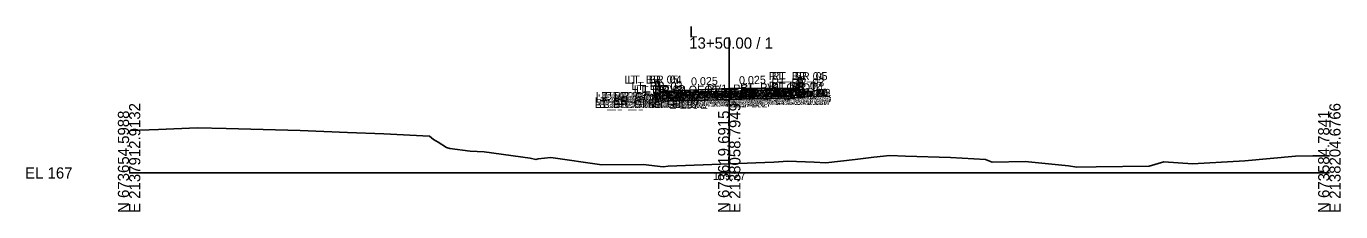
# Model space of a CAD drawing. Extents: x -26 to 5503, y -10 to 7033.
# Drawn here: x -25.7 to 302.8, y 4490.3 to 4536.7 of the extents above; entities that cross this region are included whole.
import ezdxf

# ---------------------------------------------------------------- set-up
doc = ezdxf.new("R2010")
doc.units = 0
for name, color, linetype in [('Default', 7, 'Continuous'), ('Exist Cross Section Cell', 7, 'Continuous'), ('Exist XS Center Line Elevation Label', 7, 'Continuous'), ('Exist XS Ground Line', 7, 'Continuous'), ('Prop CMT Concrete Structures', 7, 'Continuous'), ('Prop XS SE Text', 7, 'Continuous')]:
    doc.layers.add(name, color=color, linetype=linetype)

msp = doc.modelspace()

# ---------------------------------------------------------------- linework, layer by layer
at = {"layer": 'Exist Cross Section Cell'}
for p, q in [((150, 4500), (150, 4533.88)), ((0, 4500), (150, 4500)), ((150, 4500), (300, 4500))]:
    msp.add_line(p, q, dxfattribs=at)
at = {"layer": 'Exist XS Ground Line'}
for p, q in [((0.3, 4510.66), (7.34, 4510.87)), ((7.34, 4510.87), (17.04, 4511.29)), ((17.04, 4511.29), (24.28, 4511.09)), ((24.28, 4511.09), (42.73, 4510.6)), ((42.73, 4510.6), (54.62, 4510.13)), ((54.62, 4510.13), (63.65, 4509.75)), ((63.65, 4509.75), (75.1, 4509.21)), ((75.1, 4509.21), (76.09, 4508.33)), ((76.09, 4508.33), (77.25, 4507.69)), ((77.25, 4507.69), (79.37, 4506.33)), ((79.37, 4506.33), (80.21, 4506.12)), ((80.21, 4506.12), (85.28, 4505.47)), ((85.28, 4505.47), (88.71, 4505.31)), ((88.71, 4505.31), (100.28, 4503.68)), ((186.17, 4503.99), (190.12, 4504.34)), ((190.12, 4504.34), (194.06, 4504.2)), ((194.06, 4504.2), (205.31, 4503.89)), ((278.91, 4503.01), (291.58, 4504.19)), ((291.58, 4504.19), (295.84, 4504.31)), ((295.84, 4504.31), (300, 4504.25)), ((100.28, 4503.68), (101.68, 4503.38)), ((101.68, 4503.38), (102.21, 4503.51)), ((102.21, 4503.51), (105.38, 4503.9)), ((105.38, 4503.9), (118.12, 4502)), ((118.12, 4502), (128.48, 4502.12)), ((128.48, 4502.12), (133.53, 4501.5)), ((133.53, 4501.5), (134.78, 4501.66)), ((134.78, 4501.66), (150, 4502.27)), ((150, 4502.27), (161.13, 4502.71)), ((161.13, 4502.71), (164.63, 4502.91)), ((164.63, 4502.91), (171.23, 4502.74)), ((171.23, 4502.74), (174.12, 4502.5)), ((174.12, 4502.5), (181.48, 4503.34)), ((181.48, 4503.34), (186.17, 4503.99)), ((205.31, 4503.89), (214.07, 4503.38)), ((214.07, 4503.38), (215.76, 4502.68)), ((215.76, 4502.68), (224, 4502.84)), ((224, 4502.84), (234.82, 4501.75)), ((234.82, 4501.75), (236.88, 4501.48)), ((236.88, 4501.48), (241.75, 4501.55)), ((241.75, 4501.55), (254.97, 4501.69)), ((254.97, 4501.69), (258.63, 4502.77)), ((258.63, 4502.77), (265.78, 4502.28)), ((265.78, 4502.28), (278.91, 4503.01))]:
    msp.add_line(p, q, dxfattribs=at)
at = {"layer": 'Prop CMT Concrete Structures'}
for p, q in [((131.67, 4520.32), (131.69, 4522.88)), ((132.54, 4522.9), (131.69, 4522.88)), ((132.54, 4522.9), (132.69, 4520.34)), ((159.19, 4520.66), (156.18, 4520.59)), ((159.19, 4520.41), (159.19, 4520.66)), ((159.22, 4520.67), (159.22, 4520.67)), ((162.26, 4520.74), (159.25, 4520.67)), ((159.25, 4520.67), (159.26, 4520.41)), ((162.26, 4520.48), (162.26, 4520.74)), ((162.29, 4520.74), (162.29, 4520.74)), ((165.33, 4520.82), (162.32, 4520.74)), ((162.32, 4520.74), (162.33, 4520.49)), ((165.34, 4520.56), (165.33, 4520.82)), ((168.37, 4520.89), (165.36, 4520.82)), ((165.39, 4520.82), (165.4, 4520.56)), ((167.31, 4521.21), (167.33, 4523.77)), ((167.32, 4520.87), (167.31, 4521.21)), ((168.19, 4523.79), (167.33, 4523.77)), ((168.19, 4523.79), (168.34, 4521.23)), ((168.35, 4520.89), (168.34, 4521.06)), ((168.37, 4520.89), (168.43, 4520.83)), ((168.48, 4518.91), (168.43, 4520.83)), ((131.66, 4519.98), (131.59, 4519.91)), ((131.64, 4517.99), (131.59, 4519.91)), ((131.64, 4517.99), (131.71, 4517.93)), ((134.63, 4520.05), (131.66, 4519.98)), ((131.68, 4519.98), (131.67, 4520.32)), ((131.71, 4517.93), (134.65, 4518)), ((132.7, 4520), (132.69, 4520.34)), ((134.64, 4519.79), (134.61, 4519.76)), ((134.61, 4519.76), (134.61, 4519.52)), ((134.68, 4519.45), (134.61, 4519.52)), ((134.64, 4519.79), (134.63, 4520.05)), ((134.65, 4518), (134.71, 4518.07)), ((134.66, 4520.05), (134.66, 4520.05)), ((134.68, 4519.45), (134.74, 4519.52)), ((134.71, 4518.07), (134.68, 4519.45)), ((134.71, 4518.07), (134.68, 4519.45)), ((137.7, 4520.13), (134.7, 4520.05)), ((134.7, 4520.05), (134.7, 4519.8)), ((134.7, 4519.8), (134.74, 4519.76)), ((134.71, 4518.07), (134.78, 4518.01)), ((134.74, 4519.52), (134.74, 4519.76)), ((134.78, 4518.01), (137.72, 4518.08)), ((137.71, 4519.87), (137.68, 4519.84)), ((137.68, 4519.84), (137.68, 4519.59)), ((137.75, 4519.53), (137.68, 4519.59)), ((137.71, 4519.87), (137.7, 4520.13)), ((137.72, 4518.08), (137.78, 4518.14)), ((137.73, 4520.13), (137.73, 4520.13)), ((137.73, 4520.13), (137.73, 4520.13)), ((137.75, 4519.53), (137.81, 4519.6)), ((137.78, 4518.14), (137.75, 4519.53)), ((137.78, 4518.14), (137.75, 4519.53)), ((140.77, 4520.2), (137.77, 4520.13)), ((137.77, 4520.13), (137.77, 4519.87)), ((137.77, 4519.87), (137.81, 4519.84)), ((137.78, 4518.14), (137.85, 4518.08)), ((137.81, 4519.6), (137.81, 4519.84)), ((137.85, 4518.08), (140.79, 4518.16)), ((140.78, 4519.95), (140.75, 4519.92)), ((140.75, 4519.92), (140.75, 4519.67)), ((140.82, 4519.61), (140.75, 4519.67)), ((140.78, 4519.95), (140.77, 4520.2)), ((140.79, 4518.16), (140.86, 4518.22)), ((140.8, 4520.2), (140.8, 4520.2)), ((140.8, 4520.2), (140.8, 4520.2)), ((140.82, 4519.61), (140.88, 4519.67)), ((140.85, 4518.22), (140.82, 4519.61)), ((140.85, 4518.22), (140.82, 4519.61)), ((143.84, 4520.28), (140.84, 4520.21)), ((140.84, 4520.21), (140.84, 4519.95)), ((140.84, 4519.95), (140.88, 4519.92)), ((140.85, 4518.22), (140.92, 4518.16)), ((140.88, 4519.67), (140.88, 4519.92)), ((140.92, 4518.16), (143.86, 4518.23)), ((143.85, 4520.02), (143.82, 4519.99)), ((143.82, 4519.99), (143.82, 4519.75)), ((143.89, 4519.68), (143.82, 4519.75)), ((143.85, 4520.02), (143.84, 4520.28)), ((143.86, 4518.23), (143.93, 4518.3)), ((143.87, 4520.28), (143.87, 4520.28)), ((143.88, 4520.28), (143.88, 4520.28)), ((143.89, 4519.68), (143.95, 4519.75)), ((143.92, 4518.3), (143.89, 4519.68)), ((143.93, 4518.3), (143.89, 4519.68)), ((146.91, 4520.36), (143.91, 4520.28)), ((143.91, 4520.28), (143.91, 4520.03)), ((143.91, 4520.03), (143.95, 4520)), ((143.93, 4518.3), (143.99, 4518.24)), ((143.95, 4519.75), (143.95, 4520)), ((143.99, 4518.24), (146.93, 4518.31)), ((146.92, 4520.1), (146.89, 4520.07)), ((146.89, 4520.07), (146.9, 4519.82)), ((146.96, 4519.76), (146.9, 4519.82)), ((146.92, 4520.1), (146.91, 4520.36)), ((146.93, 4518.31), (147, 4518.37)), ((146.95, 4520.36), (146.95, 4520.36)), ((146.95, 4520.36), (146.95, 4520.36)), ((146.96, 4519.76), (147.02, 4519.83)), ((147, 4518.37), (146.96, 4519.76)), ((147, 4518.37), (146.96, 4519.76)), ((149.99, 4520.43), (146.98, 4520.36)), ((146.98, 4520.36), (146.99, 4520.1)), ((146.99, 4520.1), (147.02, 4520.07)), ((147, 4518.37), (147.06, 4518.31)), ((147.02, 4519.83), (147.02, 4520.07)), ((147.06, 4518.31), (150.01, 4518.39)), ((149.99, 4520.18), (149.96, 4520.15)), ((149.96, 4520.15), (149.97, 4519.9)), ((150.03, 4519.84), (149.97, 4519.9)), ((149.99, 4520.18), (149.99, 4520.43)), ((150.01, 4518.39), (150.07, 4518.45)), ((150.02, 4520.44), (150.02, 4520.44)), ((150.02, 4520.44), (150.02, 4520.44)), ((150.03, 4519.84), (150.1, 4519.9)), ((150.07, 4518.45), (150.03, 4519.84)), ((150.07, 4518.45), (150.03, 4519.84)), ((151.55, 4520.47), (150.05, 4520.44)), ((150.05, 4520.44), (150.06, 4520.18)), ((150.06, 4520.18), (150.09, 4520.15)), ((150.07, 4518.45), (150.13, 4518.39)), ((150.1, 4519.9), (150.09, 4520.15)), ((150.13, 4518.39), (151.6, 4518.43)), ((153.05, 4520.51), (151.55, 4520.47)), ((151.6, 4518.43), (153.07, 4518.46)), ((153.05, 4520.25), (153.02, 4520.22)), ((153.02, 4520.22), (153.03, 4519.98)), ((153.1, 4519.91), (153.03, 4519.98)), ((153.05, 4520.25), (153.05, 4520.51)), ((153.07, 4518.46), (153.13, 4518.53)), ((153.08, 4520.51), (153.08, 4520.51)), ((153.09, 4519.91), (153.16, 4519.98)), ((153.13, 4518.53), (153.09, 4519.91)), ((153.13, 4518.53), (153.1, 4519.91)), ((156.12, 4520.59), (153.11, 4520.51)), ((153.11, 4520.51), (153.12, 4520.26)), ((153.12, 4520.26), (153.15, 4520.23)), ((153.13, 4518.53), (153.19, 4518.47)), ((153.16, 4519.98), (153.15, 4520.23)), ((153.19, 4518.47), (156.14, 4518.54)), ((153.19, 4518.47), (156.14, 4518.54)), ((156.12, 4520.33), (156.09, 4520.3)), ((156.09, 4520.3), (156.1, 4520.05)), ((156.17, 4519.99), (156.1, 4520.05)), ((156.12, 4520.33), (156.12, 4520.59)), ((156.14, 4518.54), (156.2, 4518.6)), ((156.15, 4520.59), (156.15, 4520.59)), ((156.16, 4519.99), (156.23, 4520.06)), ((156.2, 4518.6), (156.16, 4519.99)), ((156.2, 4518.6), (156.17, 4519.99)), ((156.18, 4520.59), (156.19, 4520.33)), ((156.19, 4520.33), (156.22, 4520.3)), ((156.2, 4518.6), (156.26, 4518.54)), ((156.23, 4520.06), (156.22, 4520.3)), ((156.26, 4518.54), (159.21, 4518.62)), ((156.26, 4518.54), (159.21, 4518.62)), ((159.19, 4520.41), (159.16, 4520.38)), ((159.16, 4520.38), (159.17, 4520.13)), ((159.24, 4520.07), (159.17, 4520.13)), ((159.21, 4518.62), (159.27, 4518.68)), ((159.23, 4520.07), (159.3, 4520.13)), ((159.27, 4518.68), (159.23, 4520.07)), ((159.27, 4518.68), (159.24, 4520.07)), ((159.26, 4520.41), (159.29, 4520.38)), ((159.27, 4518.68), (159.33, 4518.62)), ((159.3, 4520.13), (159.29, 4520.38)), ((159.33, 4518.62), (162.28, 4518.69)), ((159.33, 4518.62), (162.28, 4518.69)), ((162.26, 4520.48), (162.23, 4520.45)), ((162.23, 4520.45), (162.24, 4520.21)), ((162.31, 4520.14), (162.24, 4520.21)), ((162.28, 4518.69), (162.34, 4518.76)), ((162.3, 4520.14), (162.37, 4520.21)), ((162.34, 4518.76), (162.3, 4520.14)), ((162.34, 4518.76), (162.31, 4520.14)), ((162.33, 4520.49), (162.36, 4520.46)), ((162.34, 4518.76), (162.4, 4518.7)), ((162.37, 4520.21), (162.36, 4520.46)), ((162.4, 4518.7), (165.35, 4518.77)), ((162.4, 4518.7), (165.35, 4518.77)), ((165.34, 4520.56), (165.3, 4520.53)), ((165.3, 4520.53), (165.31, 4520.28)), ((165.38, 4520.22), (165.31, 4520.28)), ((165.35, 4518.77), (165.41, 4518.84)), ((165.37, 4520.22), (165.44, 4520.29)), ((165.41, 4518.84), (165.37, 4520.22)), ((165.41, 4518.84), (165.38, 4520.22)), ((165.4, 4520.56), (165.43, 4520.53)), ((165.41, 4518.84), (165.47, 4518.77)), ((165.44, 4520.29), (165.43, 4520.53)), ((165.47, 4518.77), (168.42, 4518.85)), ((168.42, 4518.85), (168.48, 4518.91))]:
    msp.add_line(p, q, dxfattribs=at)
msp.add_lwpolyline([(132.69, 4520.35), (150, 4521.12), (167.31, 4521.21), (167.32, 4520.87), (132.7, 4520)], close=True, dxfattribs=at)
msp.add_lwpolyline([(168.35, 4520.89), (168.34, 4521.23)], dxfattribs=at)
for centre in [(132.47, 4518.97), (133.84, 4519.01), (135.54, 4519.05), (136.91, 4519.08), (138.61, 4519.13), (139.98, 4519.16), (141.68, 4519.2), (143.05, 4519.24), (144.75, 4519.28), (146.12, 4519.31), (147.83, 4519.36), (149.19, 4519.39), (150.9, 4519.43), (152.25, 4519.47), (153.96, 4519.51), (155.32, 4519.54), (157.03, 4519.59), (158.39, 4519.62), (160.1, 4519.66), (161.46, 4519.7), (163.17, 4519.74), (164.53, 4519.77), (166.24, 4519.82), (167.6, 4519.85)]:
    msp.add_circle(centre, 0.512, dxfattribs=at)

# ---------------------------------------------------------------- texts
at = {"layer": 'Default'}
for s, height, p in [('LT_ BR_05', 2, (123.82, 4522.37)), ('LT_ BR_04', 2, (124.56, 4522.37)), ('RT_ BR_04', 2, (159.87, 4523.21)), ('RT_ BR_05', 2, (160.61, 4523.21)), ('LT_BR_03', 2, (125.54, 4520.78)), ('LT_BR_02', 2, (126.13, 4519.95)), ('LT_BR_01', 2, (126.71, 4519.7)), ('LT_PV1_OEOT', 2, (128.74, 4519.82)), ('LT_BR_Girder Mid 02', 2, (132.35, 4518.6)), ('RT_BR_Girder Mid 02', 2, (133.97, 4518.64)), ('PV1_PGL', 2, (144.47, 4520.12)), ('BR_PGL', 2, (144.83, 4518.62)), ('RT_BR_Girder Out 14', 2, (147.85, 4518.98)), ('RT_BR_Girder Out 01', 2, (148.6, 4519)), ('RT_BR_Girder Out 02', 2, (148.87, 4519.02)), ('RT_PV1_OEOT', 2, (152.69, 4520.42)), ('RT_BR_07', 2, (155.01, 4518.92)), ('RT_BR_02', 2, (159.93, 4520.79)), ('RT_BR_01', 2, (160.49, 4520.54)), ('RT_BR_03', 2, (160.52, 4521.63)), ('RT_BR_06', 2, (161.38, 4519.08)), ('LT_BR_Girder Out 06', 2, (116.36, 4516.91)), ('LT_BR_Girder Out 07', 2, (116.41, 4516.24)), ('LT_BR_Girder Out 02', 2, (116.66, 4518.22)), ('LT_BR_Girder Out 03', 2, (116.66, 4517.57)), ('LT_BR_Girder Out 05', 2, (117.16, 4517.66)), ('LT_BR_Girder Out 04', 2, (117.16, 4517.07)), ('LT_BR_Girder Out 08', 2, (117.49, 4516.24)), ('LT_BR_Girder Out 01', 2, (118.06, 4518.24)), ('LT_BR_Girder Out 12', 2, (118.47, 4517.07)), ('LT_BR_Girder Out 09', 2, (118.58, 4516.24)), ('LT_BR_Girder Out 14', 2, (118.97, 4518.26)), ('LT_BR_Girder Out 13', 2, (118.97, 4517.57)), ('LT_BR_Girder Out 11', 2, (119.04, 4517.66)), ('LT_BR_Girder Out 10', 2, (119.14, 4516.91)), ('LT_BR_06', 2, (124.59, 4518.16)), ('LT_BR_07', 2, (131.06, 4518.32)), ('LT_BR_Girder Mid 06', 2, (132.05, 4517.29)), ('LT_BR_Girder Mid 07', 2, (132.1, 4516.62)), ('LT_BR_Girder Mid 03', 2, (132.35, 4517.95)), ('LT_BR_Girder Mid 05', 2, (132.85, 4518.04)), ('LT_BR_Girder Mid 04', 2, (132.85, 4517.45)), ('RT_BR_Girder Mid 05', 2, (133.47, 4518.04)), ('RT_BR_Girder Mid 04', 2, (133.47, 4517.45)), ('RT_BR_Girder Mid 03', 2, (133.97, 4517.95)), ('RT_BR_Girder Mid 06', 2, (134.17, 4517.29)), ('RT_BR_Girder Mid 07', 2, (134.22, 4516.62)), ('BR_Girder Mid 08', 2, (135.87, 4516.62)), ('RT_BR_Girder Out 09', 2, (146.95, 4517)), ('RT_BR_Girder Out 10', 2, (147.52, 4517.67)), ('RT_BR_Girder Out 13', 2, (147.85, 4518.34)), ('RT_BR_Girder Out 08', 2, (148.03, 4517)), ('RT_BR_Girder Out 12', 2, (148.35, 4517.84)), ('RT_BR_Girder Out 05', 2, (148.37, 4518.42)), ('RT_BR_Girder Out 04', 2, (148.37, 4517.84)), ('RT_BR_Girder Out 03', 2, (148.87, 4518.34)), ('RT_BR_Girder Out 11', 2, (148.91, 4518.42)), ('RT_BR_Girder Out 06', 2, (149.07, 4517.67)), ('RT_BR_Girder Out 07', 2, (149.12, 4517)), ('-', 0.0001, (0, 4500))]:
    msp.add_text(s, height=height, dxfattribs=at).set_placement(p)
at = {"layer": 'Exist Cross Section Cell'}
for s, p in [('13+50.00 / 1', (140, 4531.08)), ('L', (140, 4533.88)), ('EL 167', (-26, 4498.6))]:
    msp.add_text(s, height=2.8, dxfattribs=at).set_placement(p)
for s, p in [('N 673654.5988', (0, 4490)), ('E 2137912.9132', (2.8, 4490)), ('N 673619.6915', (150, 4490)), ('E 2138058.7949', (152.8, 4490)), ('N 673584.7841', (300, 4490)), ('E 2138204.6766', (302.8, 4490))]:
    msp.add_text(s, height=2.8, rotation=90, dxfattribs=at).set_placement(p)
at = {"layer": 'Exist XS Center Line Elevation Label'}
msp.add_text('169.27', height=2, dxfattribs=at).set_placement((145.94, 4498.27))
at = {"layer": 'Prop XS SE Text'}
for p in [(140.48, 4521.88), (152.48, 4522.18)]:
    msp.add_text('0.025', height=2, rotation=1.4321, dxfattribs=at).set_placement(p)

doc.saveas('drawing.dxf')
